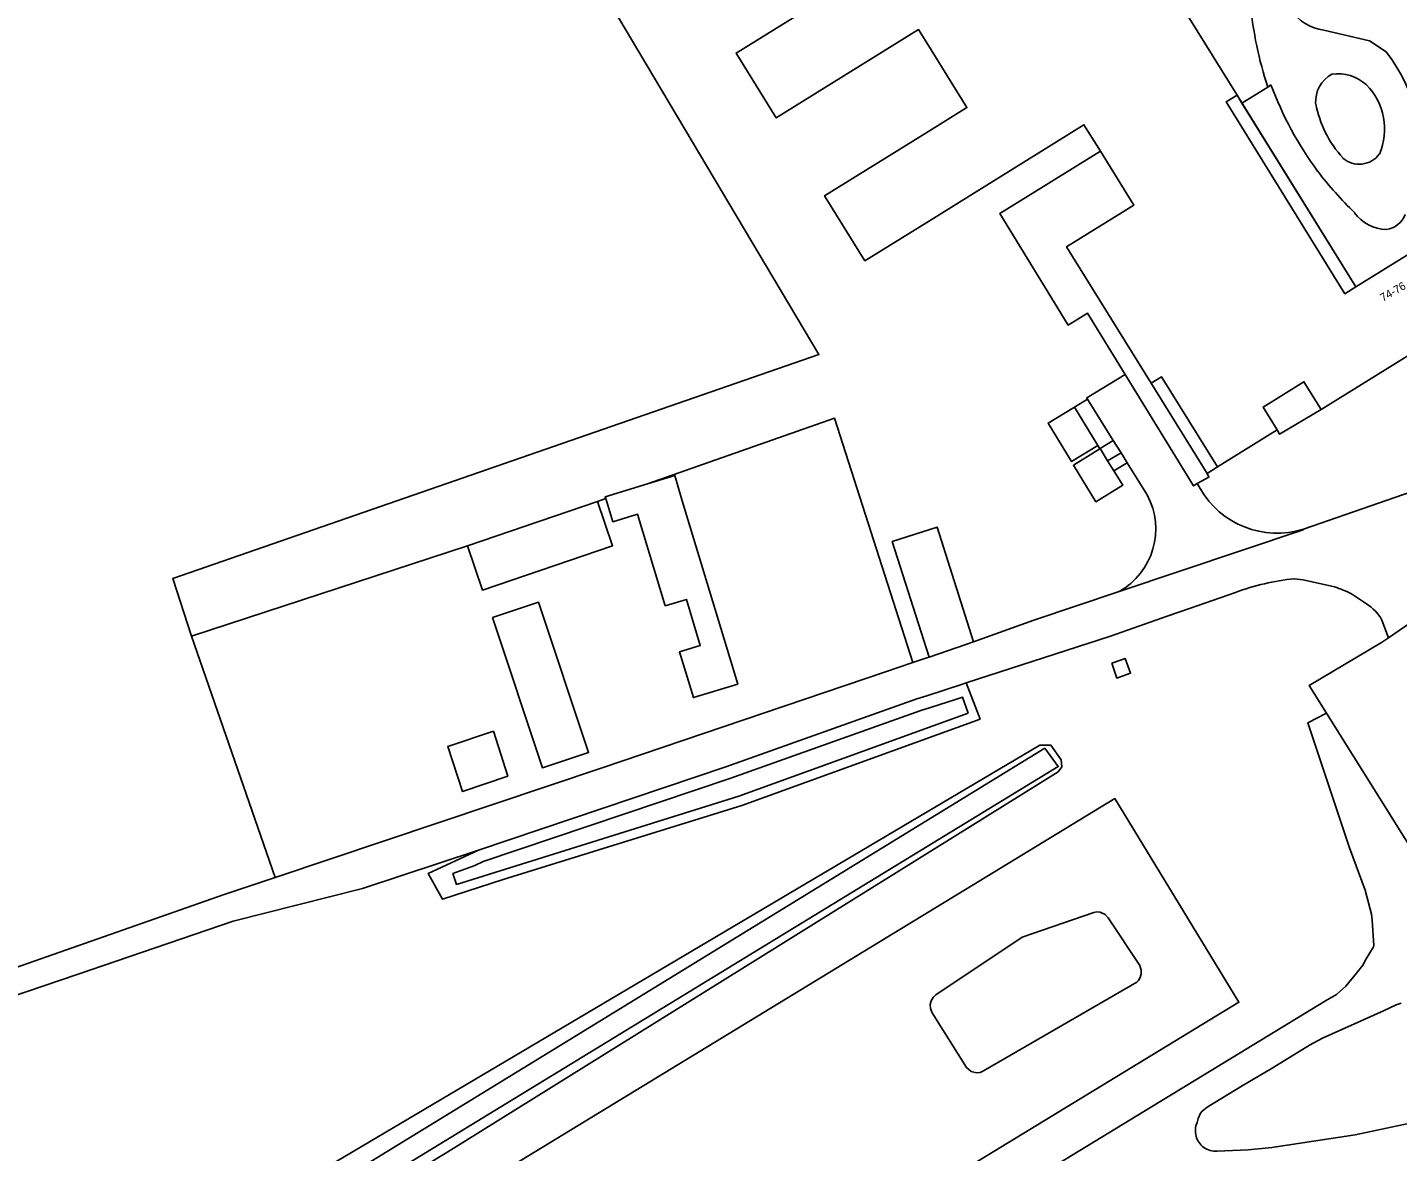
# Model space of a CAD drawing. Extents: x 158132 to 159658, y 385257 to 387209.
# Drawn here: x 158387.6 to 158558.9, y 386727.8 to 386868.4 of the extents above; entities that cross this region are included whole.
import ezdxf

# ---------------------------------------------------------------- set-up
doc = ezdxf.new("R2010")
doc.units = 0
for name, color, linetype in [('IMGEO_Gemengd_bos', 7, 'Continuous'), ('IMGEO_Grasland_overig', 7, 'Continuous'), ('IMGEO_Groenvoorziening', 7, 'Continuous'), ('IMGEO_Lage_trafo', 7, 'Continuous'), ('IMGEO_Pand', 7, 'Continuous'), ('IMGEO_Pand_nummerreeks', 7, 'Continuous'), ('IMGEO_Pand_overbouw', 7, 'Continuous'), ('IMGEO_Rijbaan_lokaal_gesloten', 7, 'Continuous'), ('IMGEO_Voetpad_open', 7, 'Continuous'), ('IMGEO_Waterloop', 7, 'Continuous')]:
    doc.layers.add(name, color=color, linetype=linetype)

msp = doc.modelspace()

# ---------------------------------------------------------------- linework, layer by layer
at = {"layer": 'IMGEO_Gemengd_bos'}
for points in [[(158408.09, 386792.27), (158405.76, 386799.46), (158486.52, 386827.49), (158458.51, 386874.59), (158467.12, 386880.53)], [(158418.54, 386762.11), (158408.09, 386792.27)]]:
    msp.add_lwpolyline(points, dxfattribs=at)
at = {"layer": 'IMGEO_Grasland_overig'}
for points in [[(158465.11, 386811.3), (158488.49, 386819.5), (158498.27, 386788.97)], [(158458.85, 386809.1), (158459.9, 386809.47)], [(158505.87, 386791.57), (158501.32, 386805.88), (158495.69, 386804.1), (158500.29, 386789.65)], [(158408.09, 386792.27), (158442.59, 386803.54)]]:
    msp.add_lwpolyline(points, dxfattribs=at)
at = {"layer": 'IMGEO_Groenvoorziening'}
for points in [[(158504.95, 386786.42), (158506.68, 386781.9), (158476.9, 386771.12), (158447.05, 386761.84), (158439.47, 386759.41), (158437.7, 386762.62), (158443.97, 386765.54)], [(158395.87, 386708.66), (158514.15, 386778.64), (158514.77, 386778.64), (158515.53, 386778.64), (158516.79, 386776.83), (158516.91, 386775.92), (158516.45, 386775.33), (158439.82, 386727.61), (158388.58, 386696.7)]]:
    msp.add_lwpolyline(points, dxfattribs=at)
at = {"layer": 'IMGEO_Lage_trafo'}
msp.add_lwpolyline([(158523.16, 386788.89), (158524.24, 386789.25), (158524.81, 386789.47), (158525.49, 386787.65), (158524.89, 386787.44), (158523.78, 386787.02), (158523.16, 386788.89)], dxfattribs=at)
at = {"layer": 'IMGEO_Pand'}
for points in [[(158506.08, 386893.26), (158516.78, 386899.9), (158521.52, 386892.26), (158520.74, 386891.76), (158524.26, 386884.41), (158525.08, 386884.85), (158528.79, 386876.02), (158538.79, 386859.9)], [(158491.24, 386880.18), (158493.79, 386876.08), (158476.17, 386865.15), (158481.2, 386857.04), (158498.99, 386868.08), (158500, 386866.44), (158505.02, 386858.34), (158500, 386855.22), (158487.24, 386847.31), (158492.27, 386839.2), (158500, 386843.99), (158519.66, 386856.18), (158521.71, 386852.88)], [(158553.66, 386835.92), (158552.28, 386835.07), (158537.42, 386859.04), (158538.79, 386859.9)], [(158521.71, 386852.88), (158525.88, 386846.15), (158517.48, 386840.94), (158528.04, 386823.9)], [(158549.3, 386820.6), (158570.34, 386833.65), (158560.86, 386840.39)], [(158553.66, 386835.92), (158560.86, 386840.39)], [(158528.04, 386823.9), (158529.33, 386824.7), (158536.33, 386813.42)], [(158543.82, 386818.06), (158542.05, 386820.91), (158547.15, 386824.07), (158549.3, 386820.6)], [(158521.39, 386816.08), (158518.11, 386814.09), (158515.18, 386818.9), (158518.46, 386820.9)], [(158518.46, 386820.9), (158521.39, 386816.08)], [(158536.33, 386813.42), (158543.82, 386818.06)], [(158521.63, 386815.68), (158518.33, 386813.64), (158521.16, 386809.07), (158524.5, 386811.14), (158523.39, 386812.93)], [(158521.67, 386815.71), (158521.63, 386815.68)], [(158522.61, 386814.19), (158521.67, 386815.71)], [(158523.39, 386812.93), (158522.61, 386814.19)], [(158459.9, 386809.47), (158460.78, 386806.56), (158463.86, 386807.5), (158467.32, 386796.07), (158469.96, 386796.87), (158471.7, 386791.1), (158469.12, 386790.32), (158470.85, 386784.6), (158476.39, 386786.28), (158469.45, 386809.19), (158468.5, 386812.33), (158465.11, 386811.3)], [(158459.9, 386809.47), (158459.83, 386809.7), (158465.11, 386811.3)], [(158442.59, 386803.54), (158458.85, 386809.1)], [(158458.85, 386809.1), (158460.74, 386803.58), (158444.48, 386798.02), (158442.59, 386803.54)], [(158445.71, 386794.59), (158451.97, 386775.82), (158457.73, 386777.74), (158451.48, 386796.51), (158445.71, 386794.59)], [(158561.73, 386794.82), (158569.83, 386750.88), (158549.96, 386782.63)], [(158557.72, 386792.05), (158561.73, 386794.82)], [(158549.96, 386782.63), (158547.79, 386786.1), (158556.86, 386791.47), (158557.72, 386792.05)], [(158445.84, 386780.39), (158440.14, 386778.48), (158441.99, 386772.84), (158447.64, 386774.78), (158445.84, 386780.39)], [(158489.45, 386716.31), (158539.03, 386746.51), (158523.53, 386771.96), (158404.59, 386699.52), (158420.09, 386674.06), (158472.88, 386706.22)], [(158507.1, 386737.92), (158506.69, 386737.75), (158506.21, 386737.7), (158505.57, 386737.85), (158504.96, 386738.35), (158500.68, 386745.17), (158500.46, 386745.74), (158500.43, 386746.23), (158500.56, 386746.71), (158500.82, 386747.12), (158501.15, 386747.42), (158511.92, 386754.66), (158520.89, 386757.75), (158521.28, 386757.8), (158521.69, 386757.76), (158522.32, 386757.46), (158522.67, 386757.07), (158526.64, 386751.09), (158526.82, 386750.53), (158526.82, 386750.06), (158526.7, 386749.61), (158526.46, 386749.23), (158526.27, 386749.02), (158507.1, 386737.92)]]:
    msp.add_lwpolyline(points, dxfattribs=at)
at = {"layer": 'IMGEO_Pand_overbouw'}
for points in [[(158538.79, 386859.9), (158537.42, 386859.04), (158552.28, 386835.07), (158553.66, 386835.92)], [(158529.33, 386824.7), (158528.04, 386823.9), (158535.04, 386812.62), (158536.33, 386813.42)]]:
    msp.add_lwpolyline(points, close=True, dxfattribs=at)
at = {"layer": 'IMGEO_Rijbaan_lokaal_gesloten'}
for points in [[(158549.63, 386868), (158555.34, 386866.68), (158557.42, 386865.29)], [(158543.03, 386861.18), (158542.63, 386860.9)], [(158524.79, 386824.97), (158520, 386822.07), (158520.09, 386821.91)], [(158533.82, 386811.33), (158533.35, 386811.05), (158524.79, 386824.97)], [(158520.09, 386821.91), (158523.32, 386816.74)], [(158523.32, 386816.74), (158524.29, 386815.19)], [(158524.29, 386815.19), (158525.06, 386813.95)], [(158525.06, 386813.95), (158527.56, 386809.94)], [(158567.49, 386812.68), (158562.73, 386811.07), (158547.09, 386805.66)], [(158534.17, 386810.74), (158533.82, 386811.33)], [(158547.09, 386805.66), (158547.07, 386805.58), (158524.05, 386797.84)], [(158550.98, 386798.43), (158547.05, 386799.33), (158545.95, 386799.45)], [(158538.58, 386797.72), (158532.85, 386795.73), (158530.06, 386794.76), (158522.98, 386792.25), (158504.95, 386786.42)], [(158524.05, 386797.84), (158513.38, 386794.25), (158505.87, 386791.57)], [(158554.98, 386796.31), (158553.09, 386797.55)], [(158557.72, 386792.05), (158556.9, 386794.28)], [(158505.87, 386791.57), (158504.89, 386791.22), (158500.29, 386789.65)], [(158498.27, 386788.97), (158494.85, 386787.8), (158459.45, 386775.83), (158418.54, 386762.11)], [(158500.29, 386789.65), (158500, 386789.55), (158498.27, 386788.97)], [(158443.97, 386765.54), (158474.89, 386775.95), (158498.78, 386784.43), (158500, 386784.82), (158504.46, 386786.26), (158504.95, 386786.42)], [(158549.96, 386782.63), (158547.63, 386781.44), (158552.84, 386765.8), (158554.79, 386760.51), (158555.58, 386757.51), (158555.7, 386756.79), (158555.91, 386753.62), (158555.83, 386753.42), (158554.92, 386751.92), (158554.53, 386751.14), (158553.73, 386750.16), (158552.38, 386748.51), (158551.24, 386747.5), (158549.85, 386746.68), (158494.74, 386713.11)], [(158443.97, 386765.54), (158429.49, 386760.75), (158413.3, 386756.63), (158393.81, 386750), (158370.72, 386742.15), (158359.23, 386738.32)], [(158418.54, 386762.11), (158412.17, 386759.98), (158383.66, 386750), (158369.81, 386745.16), (158357.85, 386741.18)], [(158553.57, 386729.96), (158543.13, 386728.35), (158540.19, 386728.06), (158536.31, 386727.91), (158536.09, 386727.9), (158535.87, 386727.91), (158535.65, 386727.94), (158535.44, 386727.99), (158535.23, 386728.05), (158535.03, 386728.14), (158534.83, 386728.24), (158534.65, 386728.36), (158534.48, 386728.49), (158534.32, 386728.64), (158534.17, 386728.8), (158534.04, 386728.97), (158533.92, 386729.16), (158533.82, 386729.35), (158533.73, 386729.55), (158533.67, 386729.76), (158533.62, 386729.98), (158533.59, 386730.19), (158533.58, 386730.41), (158533.58, 386730.63), (158533.61, 386730.85), (158533.66, 386731.06), (158533.72, 386731.27), (158533.8, 386731.47), (158533.94, 386731.99), (158534.24, 386732.64), (158534.45, 386732.91), (158534.63, 386733.05), (158535.06, 386733.38), (158539.44, 386736.07), (158543.18, 386738.26), (158547.83, 386741.13), (158549.47, 386742.04), (158557.1, 386745.45), (158558.7, 386746.2), (158559.3, 386746.38)], [(158562.57, 386731.84), (158553.57, 386729.96)]]:
    msp.add_lwpolyline(points, dxfattribs=at)
for centre, radius, start, end in [((158588.72, 386876.01), 48.5, 185.5186, 198.1481), ((158550.73, 386874.54), 6.63, 217.748, 260.4791), ((158542.62, 386853.44), 18.96, 341.8913, 38.6991), ((158552.52, 386859.08), 3.91, 118.7831, 183.6886), ((158551.41, 386857.29), 5.27, 47.9899, 98.4382), ((158585.13, 386876.96), 44.96, 200.5412, 216.2411), ((158549.31, 386855.64), 7.92, 336.6522, 44.6301), ((158562.42, 386861.49), 14.05, 190.9386, 222.3598), ((158554.08, 386854.39), 3.13, 229.1748, 322.9128), ((158585.79, 386878.61), 46.47, 217.4052, 225.9784), ((158557.61, 386848.15), 5.07, 215.7323, 268.1754), ((158557.01, 386846.07), 3.02, 278.4411, 338.3796), ((158543.77, 386816.18), 11.03, 209.5363, 287.5152), ((158519.62, 386805.68), 9.01, 299.4139, 28.202), ((158548.74, 386770.94), 28.64, 95.5759, 110.7761), ((158547.63, 386787.5), 11.43, 61.4816, 72.9388), ((158552.13, 386791.69), 5.42, 28.5085, 58.3591)]:
    msp.add_arc(centre, radius, start, end, dxfattribs=at)
at = {"layer": 'IMGEO_Voetpad_open'}
for points in [[(158542.63, 386860.9), (158539.41, 386858.9)], [(158538.79, 386859.9), (158539.41, 386858.9)], [(158539.41, 386858.9), (158553.66, 386835.92)], [(158524.79, 386824.97), (158520.1, 386832.62), (158517.7, 386831.15), (158509.14, 386845.08), (158521.71, 386852.88)], [(158528.04, 386823.9), (158535.04, 386812.62)], [(158520.09, 386821.91), (158518.46, 386820.9)], [(158549.3, 386820.6), (158544.09, 386817.52), (158543.82, 386818.06)], [(158521.39, 386816.08), (158521.63, 386815.68)], [(158523.32, 386816.74), (158521.67, 386815.71)], [(158522.61, 386814.19), (158524.29, 386815.19)], [(158525.06, 386813.95), (158523.39, 386812.93)], [(158535.04, 386812.62), (158535.27, 386812.13), (158533.82, 386811.33)], [(158536.33, 386813.42), (158535.04, 386812.62)]]:
    msp.add_lwpolyline(points, dxfattribs=at)
at = {"layer": 'IMGEO_Waterloop'}
for points in [[(158505.2, 386782.66), (158476.52, 386772.28), (158441.21, 386761.25), (158440.77, 386762.62), (158443.5, 386763.61), (158444.55, 386764.1), (158475.39, 386774.49), (158499.28, 386782.96), (158500.48, 386783.35), (158503.58, 386784.35), (158504.49, 386784.64), (158505.2, 386782.66)], [(158514.75, 386778.27), (158516.45, 386775.96), (158399.89, 386704.81), (158400.73, 386709.18), (158417.6, 386718.71), (158456.02, 386742.25), (158514.75, 386778.27)]]:
    msp.add_lwpolyline(points, dxfattribs=at)

# ---------------------------------------------------------------- texts
at = {"layer": 'IMGEO_Pand_nummerreeks'}
msp.add_text('74-76', height=1, rotation=29.9485, dxfattribs=at).set_placement((158557.04, 386834.05))

doc.saveas('drawing.dxf')
